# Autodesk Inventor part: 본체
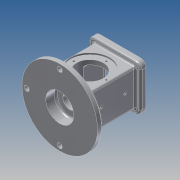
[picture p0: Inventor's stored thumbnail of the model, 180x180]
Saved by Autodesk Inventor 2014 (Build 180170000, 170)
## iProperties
Created: 2019-08
Part Number: 본체
Material: 알루미늄 6061
Document SubType Name: Modeling
Designer: kb542-11
Density: 2.71 g/cm^3
Appearance: 알루미늄 - 평지
Mass: 1042.69 g
Surface Area: 783.577 cm^2
Volume: 384.755 cm^3
Author: kb542-11
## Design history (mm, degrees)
sketch "스케치1"
  geometry: L1 (-37, -33)-(37, -33); L2 (37, -33)-(37, 33); L3 (37, 33)-(-37, 33); L4 (-37, 33)-(-37, -33); L5 (-37, -33)-(37, 33); L6 (37, -33)-(-37, 33); 1 further point
  constraints: 12 end point, 2 midpoint, 2 parallel, 1 horizontal, 1 perpendicular
  dimensions: "d0" = 74 distance of L2.end L3.end; "d1" = 66 distance of L1.end L2.end
extrude "돌출1" new body sketch "스케치1" distance "d2" = 108; taper "d3" = 0 deg
sketch "스케치2"
  geometry: L1 (-46, -41)-(46, -41); L2 (46, -41)-(46, 41); L3 (46, 41)-(-46, 41); L4 (-46, 41)-(-46, -41); L5 (-46, -41)-(46, 41); L6 (46, -41)-(-46, 41); 1 further point
  constraints: 12 end point, 2 midpoint, 2 parallel, 1 horizontal, 1 perpendicular
  dimensions: "d4" = 92 distance of L2.end L3.end; "d5" = 82 distance between parallel lines of L1 L3
extrude "돌출2" join sketch "스케치2" distance "d6" = 10; taper "d7" = 0 deg
sketch "스케치3"
  geometry: C1 r 67.5 at (0, 0); 1 further point
  constraints: 1 centre point, 1 coincident
  dimensions: "d8" = 135 diameter of C1
extrude "돌출3" join sketch "스케치3" distance "d9" = 10; taper "d10" = 0 deg
sketch "스케치4"
  geometry: L1 (104.5, -98)-(-30.5, -98) reference; C1 r 35 at (37, -44); 1 further point
  constraints: 1 centre point
  dimensions: "d11" = 70 diameter of C1; "d12" = 54 distance from line of L1 C1.centre
extrude "돌출4" cut sketch "스케치4" distance "d13" = 3; taper "d14" = 0 deg
sketch "스케치5"
  geometry: L1 (104.5, -98)-(-30.5, -98) reference; 2 further points
  dimensions: "d15" = 54 distance from line of L1 point (37, -44)
hole "구멍1" sketch "스케치5" at (37, -44) diameter "d16" = 48; stored, may be unused: countersink angle "d20" = 90 deg, drill point angle "d22" = 118 deg; dims "d17" = 6, "d18" = 70, "d19" = 3, "d21" = 8
sketch "스케치6"
  geometry: L1 (-26, -26)-(26, -26); L2 (26, -26)-(26, 26); L3 (26, 26)-(-26, 26); L4 (-26, 26)-(-26, -26); L5 (-26, -26)-(26, 26); L6 (26, -26)-(-26, 26); 1 further point
  constraints: 12 end point, 2 midpoint, 2 parallel, 1 horizontal, 1 perpendicular
  dimensions: "d23" = 52 distance of L2.end L3.end; "d24" = 52 distance of L1.end L2.end
extrude "돌출5" cut sketch "스케치6" distance "d25" = 8; taper "d26" = 0 deg
sketch "스케치7"
  geometry: L1 (-22, -22)-(22, -22); L2 (22, -22)-(22, 22); L3 (22, 22)-(-22, 22); L4 (-22, 22)-(-22, -22); L5 (-22, -22)-(22, 22); L6 (22, -22)-(-22, 22); 1 further point
  constraints: 12 end point, 2 midpoint, 2 parallel, 1 horizontal, 1 perpendicular
  dimensions: "d27" = 44 distance of L2.end L3.end; "d28" = 44 distance of L1.end L2.end
extrude "돌출6" cut sketch "스케치7" distance "d29" = 74; taper "d30" = 0 deg
sketch "스케치8"
  geometry: C1 r 67.5 at (0, 0) reference
hole "구멍2" sketch "스케치8" at (0, 0) diameter "d31" = 25; stored, may be unused: countersink angle "d35" = 90 deg, drill point angle "d37" = 118 deg; dims "d32" = 6, "d33" = 50, "d34" = 18, "d36" = 8
sketch "스케치9"
  geometry: L1 (100.5, -98)-(-34.5, -98) reference; 3 further points
  dimensions: "d38" = 37 distance from line of L1 point (33, -61); "d39" = 43 distance of point (33, -18) point (33, -61)
hole "구멍3" sketch "스케치9" at (33, -61), (33, -18) diameter "d40" = 4.917; stored, may be unused: countersink angle "d44" = 90 deg, drill point angle "d46" = 0 deg; dims "d41" = 6, "d42" = 50, "d43" = 18, "d45" = 20
fillet "모깎기1" dims "d47" = 10
sketch "스케치10"
  geometry: A1 r 10 centre (36, 31) between (46, 31) and (36, 41) reference; A2 r 10 centre (-36, 31) between (-36, 41) and (-46, 31) reference; A3 r 10 centre (-36, -31) between (-46, -31) and (-36, -41) reference; A4 r 10 centre (36, -31) between (36, -41) and (46, -31) reference; 1 further point
hole "구멍4" sketch "스케치10" at (-36, 31), (-36, -31), (36, -31), (36, 31) diameter "d48" = 3.242; stored, may be unused: countersink angle "d52" = 90 deg, drill point angle "d54" = 118 deg; dims "d49" = 4, "d50" = 50, "d51" = 18, "d53" = 6
sketch "스케치11" dims "d55" = 58
  geometry: C1 r 35 at (0, 0) reference; 3 further points
  constraints: 1 coincident, 1 vertical alignment, 2 other
hole "구멍5" sketch "스케치11" at (0, 29) diameter "d56" = 3.242; stored, may be unused: countersink angle "d60" = 90 deg, drill point angle "d62" = 118 deg; dims "d57" = 4, "d58" = 50, "d59" = 18, "d61" = 6
fillet "모깎기2" dims "d66" = 3
fillet "모깎기3" dims "d67" = 3
fillet "모깎기4" dims "d68" = 3
chamfer "모따기1" distance "d69" = 1; stored, may be unused: second distance "d70" = 2, angle "d71" = 45 deg
fillet "모깎기5" dims "d72" = 3
fillet "모깎기6" dims "d73" = 3
fillet "모깎기7" dims "d74" = 3
chamfer "모따기2" distance "d75" = 3; stored, may be unused: second distance "d76" = 2, angle "d77" = 45 deg
sketch "스케치12"
  geometry: C1 r 64.5 at (0, 0) reference; A1 r 59 centre (0, 0) between (0, 59) and (-59, 0); 1 further point
  constraints: 3 point on circle, 1 centre point, 1 coincident
  dimensions: "d78" = 118 diameter of A1
hole "구멍6" sketch "스케치12" at (0, 59), (-59, 0), (0, -59) diameter "d79" = 9; stored, may be unused: countersink angle "d83" = 90 deg, drill point angle "d85" = 118 deg; dims "d80" = 4, "d81" = 50, "d82" = 18, "d84" = 6
sketch "스케치13"
  geometry: C1 r 4.5 at (0, 59) reference; C2 r 64.5 at (0, 0) reference; 1 further point
  constraints: 1 coincident, 1 vertical alignment, 2 other
feature "엠보싱1" sketch "스케치13" dims "d0" = 74, "d1" = 66, "d86" = 0.5, "d87" = 0
node "솔리드1"
pattern_circular "원형 패턴1" dims angle "d64" = 360 deg
mirror "대칭1"
